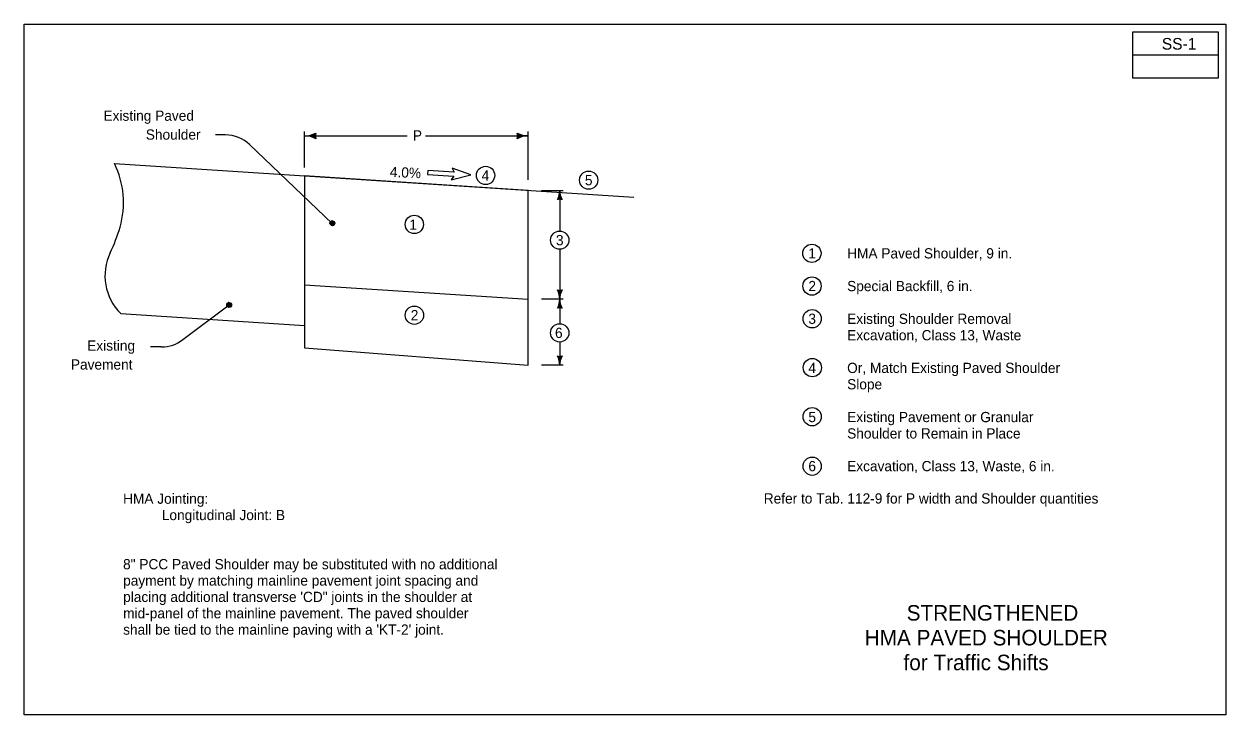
# Model space of a CAD drawing. Extents: x 6410 to 81668, y 3928 to 11667.
# Drawn here: x 13748 to 15298, y 6432 to 7323 of the extents above; entities that cross this region are included whole.
import ezdxf

# ---------------------------------------------------------------- set-up
doc = ezdxf.new("R2010")
doc.units = 0
doc.layers.add('dsnStdBlock', color=7, linetype='Continuous')
doc.layers.add('dsnStdSection', color=7, linetype='Continuous')

msp = doc.modelspace()

# ---------------------------------------------------------------- linework, layer by layer
at = {"layer": 'dsnStdBlock'}
msp.add_lwpolyline([(14109.5, 7127.6), (14109.5, 6987.2), (14398, 6968.6), (14398, 7108.9)], close=True, dxfattribs=at)
at = {"layer": 'dsnStdSection'}
for p, q in [((14007.5, 7180.4), (13994.4, 7180.4)), ((14109.5, 7138.5), (14109.5, 7184.8)), ((14398, 7122.5), (14398, 7184.8)), ((14145.1, 7066.2), (14038.6, 7167.9)), ((14109.5, 7179.2), (14241.8, 7179.2)), ((14109.6, 7179.2), (14123.4, 7179.2)), ((14265.7, 7179.2), (14398, 7179.2)), ((14398, 7179.2), (14384.2, 7179.2)), ((13864.2, 7143.5), (14534.5, 7100.1)), ((14415.3, 7108.9), (14443.3, 7108.9)), ((14438.7, 7108.9), (14438.7, 7097.5)), ((14438.7, 7108.9), (14438.7, 7056.4)), ((14438.7, 7032.9), (14438.7, 6968.6)), ((14438.7, 6968.6), (14438.7, 6980)), ((14443.3, 6968.6), (14415.3, 6968.6)), ((14438.7, 6968.8), (14438.7, 6957.4)), ((14438.7, 6968.6), (14438.7, 6936.9)), ((13872.3, 6950.2), (14109.5, 6934.8)), ((13952.4, 6916.4), (14012.4, 6961.3)), ((13924.9, 6907), (13910.9, 6907)), ((14438.7, 6913.4), (14438.7, 6883.4)), ((14438.7, 6883.4), (14438.7, 6894.8)), ((14443.3, 6883.4), (14415.3, 6883.4))]:
    msp.add_line(p, q, dxfattribs=at)
for points in [[(13747.5, 7323.5), (15298.3, 7323.5), (15298.3, 6432.2), (13747.5, 6432.2)], [(14298.8, 7122.6), (14323.8, 7128.8), (14299.7, 7137.7), (14302.3, 7132.6), (14268.5, 7134.7), (14268.1, 7129.6), (14302, 7127.4)]]:
    msp.add_lwpolyline(points, close=True, dxfattribs=at)
for points in [[(15288.3, 7313.5), (15288.3, 7253.5), (15178.3, 7253.5), (15178.3, 7313.5), (15288.3, 7313.5), (15288.3, 7283.5), (15178.3, 7283.5)], [(14123.1, 7176.6), (14122.6, 7179.2), (14123.1, 7181.8), (14120, 7180.3), (14115.1, 7179.2), (14120.4, 7178), (14122.7, 7176.9), (14122.1, 7179.2), (14122.3, 7180.9), (14120.3, 7179.9), (14117.6, 7179.2), (14120.5, 7178.4), (14122, 7177.8), (14121.7, 7180), (14119.7, 7179.2), (14121.3, 7178.7), (14121.3, 7179.5), (14120.6, 7179.2)], [(14384.5, 7181.7), (14385, 7179.2), (14384.5, 7176.6), (14387.6, 7178.1), (14392.5, 7179.2), (14387.2, 7180.4), (14384.9, 7181.4), (14385.5, 7179.2), (14385.3, 7177.5), (14387.3, 7178.5), (14390, 7179.2), (14387.1, 7180), (14385.6, 7180.5), (14385.9, 7178.3), (14387.9, 7179.2), (14386.3, 7179.7), (14386.3, 7178.9), (14387, 7179.2)], [(14109.5, 7127.8), (14109.5, 6906), (14398, 6883.4), (14398, 7108.9)], [(14436.6, 7097.7), (14438.7, 7098.2), (14440.9, 7097.7), (14439.6, 7100.3), (14438.7, 7104.3), (14437.7, 7100), (14436.9, 7098.1), (14438.7, 7098.6), (14440.1, 7098.4), (14439.3, 7100.1), (14438.7, 7102.3), (14438, 7099.9), (14437.6, 7098.7), (14439.4, 7098.9), (14438.7, 7100.6), (14438.3, 7099.2), (14438.9, 7099.2), (14438.7, 7099.8)], [(14147.7, 7068.4), (14146.6, 7068.8), (14145, 7069.6), (14143.6, 7068.6), (14142.7, 7067.4), (14142.5, 7065.7), (14143.7, 7064.7), (14145.1, 7063.7), (14146.6, 7064.1), (14147.7, 7064.9), (14148.3, 7066.9), (14147.5, 7067.9), (14146, 7068.8), (14144.3, 7069), (14143.2, 7067.8), (14143.1, 7066.2), (14144.1, 7065), (14145.5, 7064.1), (14146.3, 7064.6), (14147.3, 7065.1), (14147.7, 7066.6), (14146.9, 7067.5), (14145.7, 7068.3), (14144.5, 7068.4), (14143.9, 7067.1), (14144, 7065.8), (14145, 7064.8), (14145.8, 7065.1), (14146.7, 7065.4), (14147, 7066.6), (14146.4, 7067.5), (14145.4, 7067.8), (14144.6, 7067.1), (14144.5, 7066.3), (14145, 7065.4), (14145.5, 7065.4), (14146.1, 7065.6), (14146.4, 7066.5), (14146, 7067.1), (14145.3, 7067.3), (14145, 7066.8), (14145.1, 7066.2), (14145.5, 7065.8), (14145.9, 7066.1), (14145.6, 7066.7)], [(14440.8, 6979.7), (14438.7, 6979.3), (14436.5, 6979.8), (14437.8, 6977.2), (14438.7, 6973.2), (14439.7, 6977.5), (14440.5, 6979.4), (14438.7, 6978.9), (14437.3, 6979.1), (14438.1, 6977.4), (14438.7, 6975.2), (14439.4, 6977.6), (14439.8, 6978.8), (14438, 6978.6), (14438.7, 6976.9), (14439.1, 6978.2), (14438.5, 6978.2), (14438.7, 6977.6)], [(14014.4, 6963), (14013.3, 6963.4), (14011.8, 6964.2), (14010.4, 6963.2), (14009.5, 6962), (14009.3, 6960.3), (14010.5, 6959.3), (14011.8, 6958.3), (14013.3, 6958.7), (14014.4, 6959.6), (14015, 6961.5), (14014.3, 6962.5), (14012.8, 6963.4), (14011.1, 6963.6), (14010, 6962.4), (14009.9, 6960.8), (14010.8, 6959.7), (14012.2, 6958.7), (14013.1, 6959.2), (14014.1, 6959.8), (14014.5, 6961.3), (14013.6, 6962.1), (14012.5, 6962.9), (14011.2, 6963.1), (14010.6, 6961.7), (14010.8, 6960.4), (14011.7, 6959.4), (14012.5, 6959.7), (14013.4, 6960), (14013.7, 6961.2), (14013.2, 6962.1), (14012.2, 6962.4), (14011.4, 6961.8), (14011.2, 6960.9), (14011.7, 6960.1), (14012.3, 6960), (14012.9, 6960.2), (14013.1, 6961.2), (14012.8, 6961.7), (14012.1, 6961.9), (14011.7, 6961.5), (14011.8, 6960.9), (14012.3, 6960.4), (14012.6, 6960.8), (14012.4, 6961.3)], [(14436.6, 6957.6), (14438.7, 6958), (14440.9, 6957.6), (14439.6, 6960.1), (14438.7, 6964.2), (14437.7, 6959.8), (14436.9, 6958), (14438.7, 6958.4), (14440.1, 6958.3), (14439.3, 6959.9), (14438.7, 6962.2), (14438, 6959.8), (14437.6, 6958.5), (14439.4, 6958.8), (14438.7, 6960.4), (14438.3, 6959.1), (14438.9, 6959.1), (14438.7, 6959.7)], [(14440.8, 6894.5), (14438.7, 6894.1), (14436.5, 6894.6), (14437.8, 6892), (14438.7, 6888), (14439.7, 6892.3), (14440.5, 6894.2), (14438.7, 6893.7), (14437.3, 6893.9), (14438.1, 6892.2), (14438.7, 6890), (14439.4, 6892.4), (14439.8, 6893.6), (14438, 6893.4), (14438.7, 6891.7), (14439.1, 6893), (14438.5, 6893), (14438.7, 6892.4)]]:
    msp.add_lwpolyline(points, dxfattribs=at)
for centre, radius in [((14343, 7128.2), 11.8), ((14476, 7122.1), 11.8), ((14251.1, 7065), 11.8), ((14145.4, 7066.5), 3.15), ((14438.7, 7044.7), 11.8), ((14764, 7027.7), 11.8), ((14764.2, 6985.5), 11.8), ((14012.2, 6961.1), 3.15), ((14251.2, 6947.9), 11.8), ((14764.4, 6943.3), 11.8), ((14438.7, 6925.1), 11.8), ((14764.6, 6880.3), 11.8), ((14764.4, 6816.9), 11.8), ((14764.4, 6753.1), 11.8)]:
    msp.add_circle(centre, radius, dxfattribs=at)
for centre, radius, start, end in [((14007.5, 7135.4), 45, 46.3216, 90), ((14109.6, 7209.8), 30.6, 270, 298.0725), ((14135.2, 7179.2), 11.8, 162.2666, 197.7334), ((14372.4, 7179.2), 11.8, 342.2666, 17.7334), ((14398, 7209.8), 30.6, 241.9275, 270), ((14109.6, 7148.6), 30.6, 61.9275, 90), ((14398, 7148.6), 30.6, 90, 118.0725), ((13762.9, 7093.3), 113, 343.6708, 26.3373), ((14413.5, 7108.9), 25.2, 331.9275, 360), ((14463.9, 7108.9), 25.2, 180, 208.0725), ((14438.7, 7087.7), 9.75, 72.2666, 107.7334), ((13658.9, 7123.8), 221.4, 334.4332, 343.6708), ((13920.1, 6998.9), 68.2, 154.4332, 225.5564), ((14438.7, 6989.7), 9.75, 252.2666, 287.7334), ((14413.5, 6968.6), 25.2, 360, 28.0725), ((14463.9, 6968.6), 25.2, 151.9275, 180), ((14413.5, 6968.8), 25.2, 331.9275, 360), ((14463.9, 6968.8), 25.2, 180, 208.0725), ((14438.7, 6947.6), 9.75, 72.2666, 107.7334), ((13924.9, 6952), 45, 270, 307.6187), ((14438.7, 6904.5), 9.75, 252.2666, 287.7334), ((14413.5, 6883.4), 25.2, 360, 28.0725), ((14463.9, 6883.4), 25.2, 151.9275, 180)]:
    msp.add_arc(centre, radius, start, end, dxfattribs=at)

# ---------------------------------------------------------------- texts
for s, height, p in [('SS-1', 15, (15215.5, 7290.5)), ('Existing Paved', 13.2, (13850, 7198.7)), ('Shoulder', 13.2, (13904.6, 7174.3)), ('P', 13.2, (14249.2, 7173.2)), ('4', 13.2, (14337.9, 7121.6)), ('5', 13.2, (14471.2, 7115.5)), ('1', 13.2, (14244.6, 7058.1)), ('3', 13.2, (14433.8, 7038.1)), ('1', 13.2, (14759.5, 7021.1)), ('HMA Paved Shoulder, 9 in.', 13.2, (14809.5, 7021.1)), ('2', 13.2, (14759.5, 6978.9)), ('Special Backfill, 6 in.', 13.2, (14809.5, 6978.9)), ('2', 13.2, (14246.5, 6941.3)), ('3', 13.2, (14759.5, 6936.7)), ('Existing Shoulder Removal ', 13.2, (14809.5, 6936.7)), ('6', 13.2, (14432.6, 6918.5)), ('Excavation, Class 13, Waste', 13.2, (14809.5, 6915.5)), ('Existing', 13.2, (13829, 6902.1)), ('Pavement', 13.2, (13808, 6877.7)), ('4', 13.2, (14759.5, 6873.3)), ('Or, Match Existing Paved Shoulder ', 13.2, (14809.5, 6873.3)), ('Slope', 13.2, (14809.5, 6852.2)), ('Existing Pavement or Granular ', 13.2, (14809.5, 6809.9)), ('5', 13.2, (14759.5, 6809.9)), ('Shoulder to Remain in Place', 13.2, (14809.5, 6788.8)), ('6', 13.2, (14759.5, 6746.6)), ('Excavation, Class 13, Waste, 6 in.', 13.2, (14809.5, 6746.6)), ('HMA Jointing:', 13.2, (13875.3, 6704.6)), ('Refer to Tab. 112-9 for P width and Shoulder quantities', 13.2, (14701.9, 6704.9)), ('Longitudinal Joint: B', 13.2, (13925.3, 6683.5)), ('8" PCC Paved Shoulder may be substituted with no additional ', 13.2, (13875.3, 6620.1)), ('payment by matching mainline pavement joint spacing and ', 13.2, (13875.4, 6599)), ('placing additional transverse \'CD" joints in the shoulder at ', 13.2, (13875.4, 6577.9)), ('mid-panel of the mainline pavement. The paved shoulder ', 13.2, (13875.4, 6556.8)), ('STRENGTHENED ', 20, (14886.3, 6553.9)), ("shall be tied to the mainline paving with a 'KT-2' joint.", 13.2, (13875.4, 6535.7)), ('HMA PAVED SHOULDER', 20, (14832.2, 6521.9)), ('for Traffic Shifts', 20, (14882.2, 6489.9))]:
    msp.add_text(s, height=height, dxfattribs=at).set_placement(p)
msp.add_text('4.0%', height=13.2, rotation=357.4961, dxfattribs=at).set_placement((14219.3, 7126.3))

doc.saveas('drawing.dxf')
